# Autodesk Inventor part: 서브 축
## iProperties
Created: 2014-10
Part Number: 서브 축
Document SubType Name: Modeling
Designer: KYOUNG IL JANG
Density: 1 g/cm^3
Mass: 19.9624 g
Surface Area: 57.7178 cm^2
Volume: 19.9624 cm^3
Author: SeoGD™ [www.esajin.kr]
Revision Number: 1
